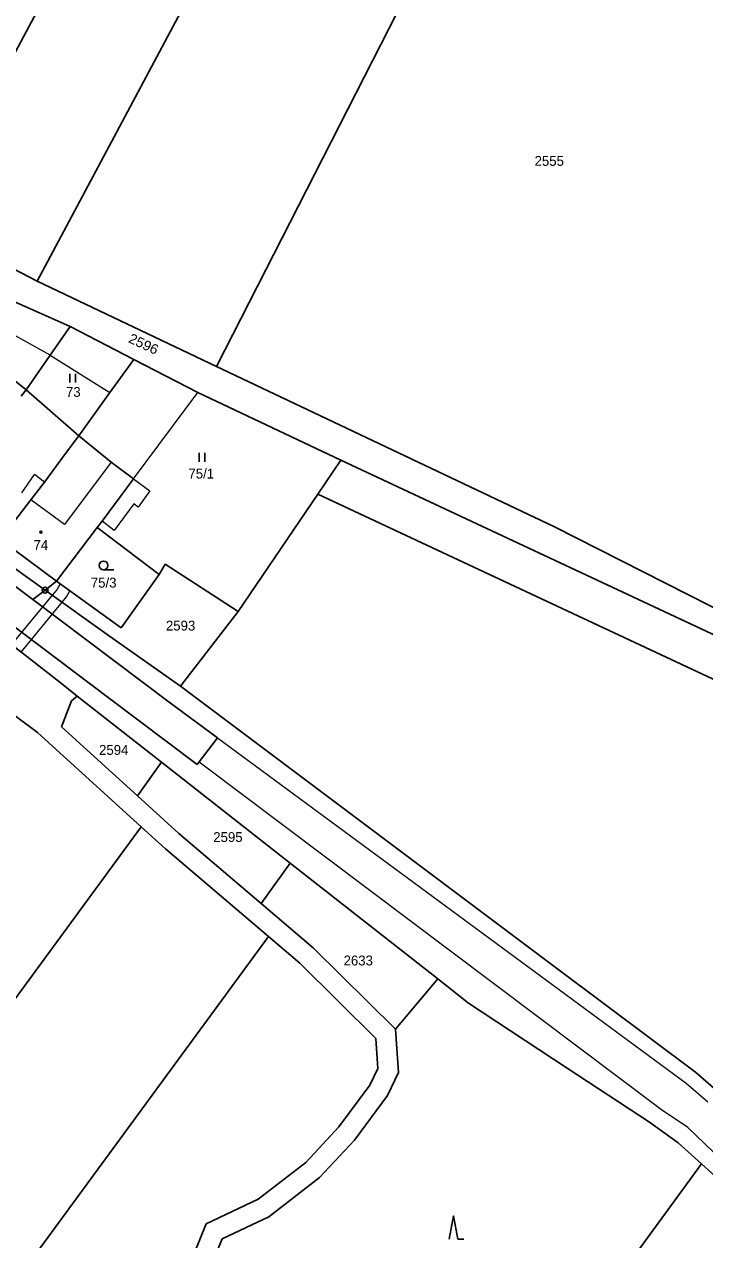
# Model space of a CAD drawing. Extents: x -606517 to -602431, y -1183120 to -1179397.
# Drawn here: x -605119 to -605001.8, y -1181219.7 to -1181010.4 of the extents above; entities that cross this region are included whole.
import ezdxf

# ---------------------------------------------------------------- set-up
doc = ezdxf.new("R2010")
doc.units = 0
doc.header["$LTSCALE"] = 0.68
for name, color, linetype, lineweight in [('1', 7, 'Continuous', 25), ('13', 7, 'Continuous', 13), ('3', 7, 'Continuous', 25), ('4', 7, 'Continuous', 13), ('5', 7, 'Continuous', 25), ('8', 7, 'Continuous', 25)]:
    doc.layers.add(name, color=color, linetype=linetype, lineweight=lineweight)
doc.layers.add('2', color=7, linetype='Continuous')

msp = doc.modelspace()

# ---------------------------------------------------------------- linework, layer by layer
at = {"layer": '1'}
for p, q in [((-605076.15, -1180931.95), (-605136.19, -1181044.52)), ((-605116.76, -1181054.62), (-605051.07, -1180931.45)), ((-605085.89, -1181069.32), (-605033.27, -1180966.33)), ((-605136.19, -1181044.52), (-605116.76, -1181054.62)), ((-605115.56, -1181055.24), (-605116.76, -1181054.62)), ((-605085.89, -1181069.32), (-605115.56, -1181055.24)), ((-605121.89, -1181057.63), (-605111.06, -1181062.46)), ((-605114.49, -1181067.38), (-605111.06, -1181062.46)), ((-605111.06, -1181062.46), (-605100.12, -1181068.14)), ((-605128, -1181065.78), (-605118.66, -1181073.37)), ((-605118.66, -1181073.37), (-605114.49, -1181067.38)), ((-605104.21, -1181073.82), (-605100.12, -1181068.14)), ((-605100.12, -1181068.14), (-605089.06, -1181073.81)), ((-605027.68, -1181096.94), (-605085.89, -1181069.32)), ((-605119.53, -1181074.46), (-605118.66, -1181073.37)), ((-605118.66, -1181073.37), (-605109.58, -1181081.28)), ((-605109.58, -1181081.28), (-605104.21, -1181073.82)), ((-605089.06, -1181073.81), (-605064.44, -1181085.46)), ((-605109.58, -1181081.28), (-605111.85, -1181084.33)), ((-605104, -1181085.83), (-605109.58, -1181081.28)), ((-605115.48, -1181089.26), (-605111.85, -1181084.33)), ((-605100.16, -1181088.67), (-605104, -1181085.83)), ((-605064.44, -1181085.46), (-605068.42, -1181091.31)), ((-604995.57, -1181117.73), (-605064.44, -1181085.46)), ((-605105.57, -1181095.97), (-605100.16, -1181088.67)), ((-605115.48, -1181089.26), (-605117.81, -1181092.28)), ((-605117.81, -1181092.28), (-605123.05, -1181099.14)), ((-605068.42, -1181091.31), (-605082.15, -1181111.52)), ((-605134.38, -1181094.27), (-605115.39, -1181107.85)), ((-605113.42, -1181106.3), (-605106.42, -1181097.09)), ((-605106.42, -1181097.09), (-605105.57, -1181095.97)), ((-605106.42, -1181097.09), (-605095.74, -1181105.14)), ((-604995.84, -1181113.11), (-605027.68, -1181096.94)), ((-605131.39, -1181099.08), (-605117.47, -1181109.49)), ((-605123.05, -1181099.14), (-605113.42, -1181106.3)), ((-605094.73, -1181103.4), (-605095.74, -1181105.14)), ((-605082.15, -1181111.52), (-605094.73, -1181103.4)), ((-605095.74, -1181105.14), (-605102.27, -1181114.35)), ((-605113.42, -1181106.3), (-605115.39, -1181107.85)), ((-605102.27, -1181114.35), (-605113.42, -1181106.3)), ((-605115.39, -1181107.85), (-605117.47, -1181109.49)), ((-605093.99, -1181127.17), (-605117.47, -1181109.49)), ((-605115.39, -1181107.85), (-605104.3, -1181115.79)), ((-605092.06, -1181124.42), (-605082.15, -1181111.52)), ((-605122.06, -1181113.11), (-605104.5, -1181126.35)), ((-605104.3, -1181115.79), (-605092.06, -1181124.42)), ((-605112.86, -1181123.73), (-605120.87, -1181117.45)), ((-605109.86, -1181126.09), (-605112.86, -1181123.73)), ((-605092.06, -1181124.42), (-605053.75, -1181153.13)), ((-605116.67, -1181132.36), (-605127.15, -1181124.63)), ((-605109.86, -1181126.09), (-605110.81, -1181126.94)), ((-605095.34, -1181137.48), (-605109.86, -1181126.09)), ((-605104.5, -1181126.35), (-605089.17, -1181137.91)), ((-605110.81, -1181126.94), (-605112.54, -1181131.39)), ((-605112.54, -1181131.39), (-605099.48, -1181143.27)), ((-605095.34, -1181137.48), (-605099.48, -1181143.27)), ((-605073.2, -1181154.86), (-605095.34, -1181137.48)), ((-605099.48, -1181143.27), (-605092.34, -1181149.77)), ((-605168.54, -1181243.67), (-605098.83, -1181148.6)), ((-605092.34, -1181149.77), (-605078.18, -1181161.83)), ((-605076.93, -1181167.5), (-605094.65, -1181152.4)), ((-605053.75, -1181153.13), (-605027.08, -1181173.11)), ((-605073.2, -1181154.86), (-605078.18, -1181161.83)), ((-605047.76, -1181174.83), (-605073.2, -1181154.86)), ((-605078.18, -1181161.83), (-605069.15, -1181169.53)), ((-605150.74, -1181268.16), (-605076.93, -1181167.5)), ((-605076.93, -1181167.5), (-605071.52, -1181172.11)), ((-605069.15, -1181169.53), (-605055.07, -1181183.48)), ((-605071.52, -1181172.11), (-605058.46, -1181185.05)), ((-605027.08, -1181173.11), (-605003.38, -1181190.87)), ((-605055.07, -1181183.48), (-605047.76, -1181174.83)), ((-605047.76, -1181174.83), (-605042.48, -1181178.97)), ((-605042.48, -1181178.97), (-605025.46, -1181190.17)), ((-605058.46, -1181185.05), (-605058.07, -1181190.26)), ((-605054.51, -1181190.94), (-605055.07, -1181183.48)), ((-605058.07, -1181190.26), (-605059.44, -1181193.09)), ((-605056.44, -1181194.91), (-605054.51, -1181190.94)), ((-605025.46, -1181190.17), (-605011.31, -1181199.47)), ((-605003.38, -1181190.87), (-604999.9, -1181193.94)), ((-605059.44, -1181193.09), (-605064.82, -1181200.32)), ((-605062.12, -1181202.56), (-605056.44, -1181194.91)), ((-605011.31, -1181199.47), (-605006.37, -1181203.02)), ((-605064.82, -1181200.32), (-605070.48, -1181206.42)), ((-605068.11, -1181209.01), (-605062.12, -1181202.56)), ((-605006.37, -1181203.02), (-605002.33, -1181206.68)), ((-605070.48, -1181206.42), (-605078.67, -1181212.77)), ((-605002.33, -1181206.68), (-605075.48, -1181306.41)), ((-604987.82, -1181219.82), (-605002.33, -1181206.68)), ((-605076.83, -1181215.77), (-605068.11, -1181209.01)), ((-605078.67, -1181212.77), (-605087.64, -1181216.98)), ((-605084.92, -1181219.57), (-605076.83, -1181215.77)), ((-605087.64, -1181216.98), (-605090.9, -1181224.96)), ((-605087.64, -1181226.23), (-605084.92, -1181219.57))]:
    msp.add_line(p, q, dxfattribs=at)
for points in [[(-604855.57, -1181294.85), (-604902.72, -1181270.57), (-604916.88, -1181256.29), (-604924.34, -1181237.29), (-604922.12, -1181215.85), (-604912.33, -1181197.46), (-604903.07, -1181181.59), (-604903.42, -1181175.71), (-604908.72, -1181170.89), (-604916.94, -1181163.39), (-604933.53, -1181154.48), (-604960.93, -1181142.61), (-604963.71, -1181141.34), (-604966.84, -1181140.17), (-604998.64, -1181124.02), (-605068.42, -1181091.31)], [(-605093.99, -1181127.17), (-605085.67, -1181133.3), (-605089.17, -1181137.91)], [(-605094.65, -1181152.4), (-605098.83, -1181148.6), (-605116.67, -1181132.36)]]:
    msp.add_lwpolyline(points, dxfattribs=at)
at = {"layer": '13'}
msp.add_lwpolyline([(-605119.51, -1181118.51), (-605112.47, -1181109.94), (-605111.68, -1181108.98), (-605111.12, -1181107.96), (-605112.8, -1181106.75), (-605113.37, -1181107.78), (-605114.15, -1181108.73), (-605121.14, -1181117.24)], close=True, dxfattribs=at)
at = {"layer": '3'}
for p, q in [((-605111.141, -1181072.1), (-605111.141, -1181070.6)), ((-605110.14, -1181072.1), (-605110.14, -1181070.6)), ((-605088.851, -1181085.73), (-605088.851, -1181084.23)), ((-605087.85, -1181085.73), (-605087.85, -1181084.23)), ((-605105.303, -1181104.34), (-605103.553, -1181104.34)), ((-605044.29, -1181219.64), (-605043.294, -1181219.64))]:
    msp.add_line(p, q, dxfattribs=at)
msp.add_lwpolyline([(-605044.29, -1181219.64), (-605045.04, -1181215.64), (-605045.79, -1181219.64)], dxfattribs=at)
msp.add_circle((-605105.3029, -1181103.5898), 0.75, dxfattribs=at)
at = {"layer": '4'}
for p, q in [((-605114.49, -1181067.38), (-605124.89, -1181061.63)), ((-605114.49, -1181067.38), (-605104.21, -1181073.82)), ((-605100.16, -1181088.67), (-605089.06, -1181073.81)), ((-605104, -1181085.83), (-605112.04, -1181096.53)), ((-605119.39, -1181091.07), (-605117.21, -1181087.96)), ((-605115.48, -1181089.26), (-605117.21, -1181087.96)), ((-605100.16, -1181088.67), (-605097.36, -1181090.75)), ((-605097.36, -1181090.75), (-605099.36, -1181093.54)), ((-605112.04, -1181096.53), (-605117.81, -1181092.28)), ((-605100.12, -1181092.99), (-605103.48, -1181097.56)), ((-605099.36, -1181093.54), (-605100.12, -1181092.99)), ((-605103.48, -1181097.56), (-605105.57, -1181095.97)), ((-605085.67, -1181133.3), (-605005.01, -1181192.79)), ((-605009.23, -1181197.34), (-605088.84, -1181137.48)), ((-605005.01, -1181192.79), (-605001.28, -1181196.01)), ((-605004.69, -1181200.39), (-605009.23, -1181197.34))]:
    msp.add_line(p, q, dxfattribs=at)
msp.add_lwpolyline([(-604935.53, -1181475.1), (-604936.88, -1181448.29), (-604964.29, -1181275.49), (-604967.63, -1181256.05), (-604973.53, -1181239.25), (-604985.7, -1181218.67), (-605004.69, -1181200.39)], dxfattribs=at)
at = {"layer": '5'}
msp.add_circle((-605116.0968, -1181097.8692), 0.175, dxfattribs=at)
at = {"layer": '8'}
for radius in [0.5, 0.0303]:
    msp.add_circle((-605115.39, -1181107.8499), radius, dxfattribs=at)

# ---------------------------------------------------------------- texts
at = {"layer": '2'}
for s, p in [('2555', (-605031.1, -1181034.775)), ('73', (-605111.79, -1181074.565)), ('75/1', (-605090.7, -1181088.635)), ('74', (-605117.38, -1181100.945)), ('75/3', (-605107.51, -1181107.415)), ('2593', (-605094.58, -1181114.815)), ('2594', (-605106.09, -1181136.225)), ('2595', (-605086.43, -1181151.235)), ('2633', (-605063.99, -1181172.495))]:
    msp.add_text(s, height=1.7, dxfattribs=at).set_placement(p)
at = {"layer": '2', "width": 1.05}
msp.add_text('2596', height=1.7, rotation=335, dxfattribs=at).set_placement((-605101.179, -1181065.105))

doc.saveas('drawing.dxf')
